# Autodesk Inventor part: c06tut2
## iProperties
Shininess: 77.0
Length Units: 11269
Angle Units: 11279
Time Units: 11290
Mass Units: 11283
Length Display Precision: 3
Angle Display Precision: 2
Created: 2001-12
Part Number: c06tut2
Document SubType Name: Modeling
Designer: Renu Muthoo
Density: 0.0
Volumn: 0.0
Area: 0.0
PropertySet Name: Model Information
Control State: 0
Master: False
Checked Out: False
Author: Renu Muthoo
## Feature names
1. Extrusion1
2. Hole1
3. Extrusion2
4. Extrusion3
5. Extrusion4
6. Extrusion5
7. Hole2
8. Hole3
9. Hole4
